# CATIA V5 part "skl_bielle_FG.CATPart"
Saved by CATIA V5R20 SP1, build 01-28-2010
Part number: skl_bielle_FG
Publications: "Droite.1", "Droite.2", "Plan.1", "Point.1", "F", "Droite.3"
Bounding box of the stored display mesh (mm): x -20.434 to 29.779, y -20 to 0, z 82.679 to 102.679
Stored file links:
  C:\Users\Matthieu\Desktop\IAO_2012_mcamard_Catia\skl_bielle_FG.CATPart
  C:\Users\Matthieu\Desktop\IAO_Artobolevsky\skl_Artoboloevsky_786.CATProduct
  C:\Users\Matthieu\Desktop\IAO_2012_mcamard_Catia\skl_bielle_EF.CATPart
  C:\Users\Matthieu\Desktop\IAO_2012_mcamard_Catia\skl_general.CATPart
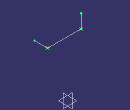
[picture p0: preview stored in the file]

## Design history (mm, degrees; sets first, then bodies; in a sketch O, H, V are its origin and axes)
Set1
  Point1 "F": linked copy from another document
  DatumPoint1: linked copy from another document
  Plane1: linked copy from another document
Set2
  Line1: type PtPt, FirstPoint Point1, SecondPoint DatumPoint1
  Line2: type Normal, RefPoint Point1, RefSkin Plane1, Start 0, End 20
  Line3: type Angle, RefPoint DatumPoint1, Curve Line1, Support zx-plane, Start 0, End 20, Angle 90
Body1 (main body)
